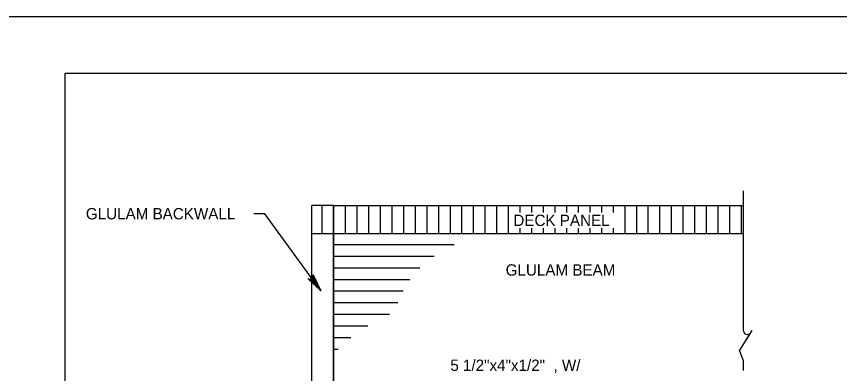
# Model space of a CAD drawing. Extents: x 638263 to 640391, y 293683 to 298655.
# Drawn here: x 639303.6 to 639521, y 298341 to 298435.5 of the extents above; entities that cross this region are included whole.
import ezdxf

# ---------------------------------------------------------------- set-up
doc = ezdxf.new("R2010")
doc.units = 0
for name, color, linetype in [('2', 7, 'Continuous'), ('3', 7, 'Continuous'), ('4', 7, 'Continuous'), ('5', 7, 'Continuous'), ('7', 7, 'Continuous'), ('PLT-BNDY', 7, 'Continuous')]:
    doc.layers.add(name, color=color, linetype=linetype)

msp = doc.modelspace()

# ---------------------------------------------------------------- linework, layer by layer
at = {"layer": '2'}
for p, q in [((639316.46, 297856.46), (639316.46, 298420.46)), ((639316.46, 298420.46), (640102.46, 298420.46))]:
    msp.add_line(p, q, dxfattribs=at)
at = {"layer": '3'}
for p, q in [((639369.18, 298383.26), (639366.23, 298383.26)), ((639383.93, 298362.9), (639369.18, 298383.26))]:
    msp.add_line(p, q, dxfattribs=at)
msp.add_lwpolyline([(639383.93, 298362.9), (639380.49, 298366.16), (639380.9, 298366.01), (639381.26, 298366.05), (639381.55, 298366.19), (639381.77, 298366.41), (639381.91, 298366.75), (639381.9, 298367.18), (639383.93, 298362.9), (639381.91, 298366.75), (639381.77, 298366.41), (639383.93, 298362.9), (639381.55, 298366.19), (639381.26, 298366.05), (639383.93, 298362.9), (639380.9, 298366.01)], dxfattribs=at)
at = {"layer": '5'}
for p, q in [((639495.53, 298389.38), (639495.53, 298352.47)), ((639381.56, 298308.06), (639381.56, 298385.48)), ((639387.33, 298385.48), (639381.56, 298385.48)), ((639384.25, 298385.48), (639384.25, 298378.04)), ((639387.33, 298308.06), (639387.33, 298385.48)), ((639387.33, 298385.48), (639387.33, 298378.04)), ((639387.33, 298385.48), (639495.53, 298385.48)), ((639390.4, 298385.48), (639390.4, 298378.04)), ((639393.48, 298385.48), (639393.48, 298378.04)), ((639396.56, 298385.48), (639396.56, 298378.04)), ((639399.63, 298385.48), (639399.63, 298378.04)), ((639402.71, 298385.48), (639402.71, 298378.04)), ((639405.78, 298385.48), (639405.78, 298378.04)), ((639408.86, 298385.48), (639408.86, 298378.04)), ((639411.93, 298385.48), (639411.93, 298378.04)), ((639415.01, 298385.48), (639415.01, 298378.04)), ((639418.09, 298385.48), (639418.09, 298378.04)), ((639421.16, 298385.48), (639421.16, 298378.04)), ((639424.24, 298385.48), (639424.24, 298378.04)), ((639427.31, 298385.48), (639427.31, 298378.04)), ((639430.39, 298385.48), (639430.39, 298378.04)), ((639433.46, 298385.48), (639433.46, 298378.04)), ((639436.54, 298385.48), (639436.54, 298383.66)), ((639439.62, 298385.48), (639439.62, 298383.66)), ((639442.69, 298385.48), (639442.69, 298383.66)), ((639445.77, 298385.48), (639445.77, 298383.66)), ((639448.84, 298385.48), (639448.84, 298383.66)), ((639451.92, 298385.48), (639451.92, 298383.66)), ((639455, 298385.48), (639455, 298383.66)), ((639458.07, 298385.48), (639458.07, 298383.66)), ((639461.15, 298385.48), (639461.15, 298383.66)), ((639464.22, 298385.48), (639464.22, 298378.04)), ((639467.3, 298385.48), (639467.3, 298378.04)), ((639470.37, 298385.48), (639470.37, 298378.04)), ((639473.45, 298385.48), (639473.45, 298378.04)), ((639476.52, 298385.48), (639476.52, 298378.04)), ((639479.6, 298385.48), (639479.6, 298378.04)), ((639482.68, 298385.48), (639482.68, 298378.04)), ((639485.75, 298385.48), (639485.75, 298378.04)), ((639488.83, 298385.48), (639488.83, 298378.04)), ((639491.9, 298385.48), (639491.9, 298378.04)), ((639494.98, 298385.48), (639494.98, 298378.04)), ((639381.56, 298378.04), (639495.53, 298378.04)), ((639387.33, 298378.04), (639387.33, 298308.06)), ((639436.54, 298379.44), (639436.54, 298378.04)), ((639439.62, 298379.44), (639439.62, 298378.04)), ((639442.69, 298379.44), (639442.69, 298378.04)), ((639445.77, 298379.44), (639445.77, 298378.04)), ((639448.84, 298379.44), (639448.84, 298378.04)), ((639451.92, 298379.44), (639451.92, 298378.04)), ((639455, 298379.44), (639455, 298378.04)), ((639458.07, 298379.44), (639458.07, 298378.04)), ((639461.15, 298379.44), (639461.15, 298378.04)), ((639497.8, 298352.39), (639494.54, 298347.21)), ((639495.53, 298344.62), (639494.54, 298347.21)), ((639495.53, 298344.62), (639495.53, 298341.87))]:
    msp.add_line(p, q, dxfattribs=at)
msp.add_arc((639496.59, 298352.47), 1.07, 180, 330, dxfattribs=at)
at = {"layer": '7'}
for p, q in [((639387.33, 298375.17), (639419.21, 298375.17)), ((639387.33, 298372.1), (639413.87, 298372.1)), ((639387.33, 298369.02), (639410.11, 298369.02)), ((639387.33, 298365.94), (639407.49, 298365.94)), ((639387.33, 298362.87), (639405.71, 298362.87)), ((639387.33, 298359.79), (639404.32, 298359.79)), ((639387.33, 298356.72), (639402.1, 298356.72)), ((639387.33, 298353.64), (639396.41, 298353.64)), ((639387.33, 298350.56), (639391.9, 298350.56)), ((639387.33, 298347.49), (639388.54, 298347.49))]:
    msp.add_line(p, q, dxfattribs=at)
at = {"layer": 'PLT-BNDY'}
msp.add_lwpolyline([(639276.46, 298435.46), (640117.46, 298435.46), (640117.46, 297841.46), (639276.46, 297841.46)], close=True, dxfattribs=at)

# ---------------------------------------------------------------- texts
at = {"layer": '3'}
for s, p in [('GLULAM BACKWALL', (639321.91, 298381.8)), ('DECK PANEL', (639434.82, 298380.05)), ('GLULAM BEAM', (639432.78, 298366.93))]:
    msp.add_text(s, height=3, dxfattribs=at).set_placement(p)
at = {"layer": '4'}
msp.add_text('5 1/2"x4"x1/2"  , W/', height=3, dxfattribs=at).set_placement((639418.17, 298341.73))

doc.saveas('drawing.dxf')
